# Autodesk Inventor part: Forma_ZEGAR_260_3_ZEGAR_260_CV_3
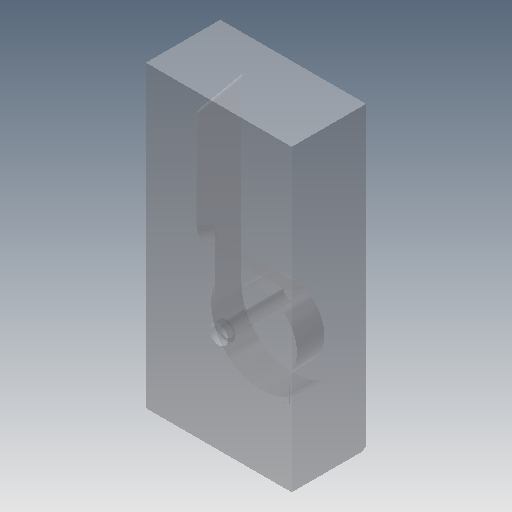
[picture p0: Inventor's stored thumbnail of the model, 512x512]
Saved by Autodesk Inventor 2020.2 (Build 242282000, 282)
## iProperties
Created: 2015-01
Part Number: Forma_ZEGAR_260_3_ZEGAR_260_CV_3
Material: Ogólny
Document SubType Name: Modeling
Designer: F.Stasiak
Density: 1 g/cm^3
Appearance: Domyślna
Catalog Web Link: www.expertbooks.pl
Manager: www.cadconsulting.pl
Company: Fabian Stasiak CAD Consulting
Author: F.Stasiak
Subject: Zbiór ćwiczeń. Autodesk Inventor 2020. Kurs Professional
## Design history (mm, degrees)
node "Forma_ZEGAR_260_3_ZEGAR_260_CV_Base"
feature "Rzeźbienie3"
feature "Bryła1::Forma_ZEGAR_260_3_ZEGAR_260_CV_Base"
tag "Bryła wyprowadzona1"
node "Bryła1"
feature "Forma_ZEGAR_260_3_ZEGAR_260_CV_Base_Bodies"
feature "Powierzchnia3"
body "Srf3"
